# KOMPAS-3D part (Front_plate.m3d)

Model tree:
1. X Axis
2. Y Axis
3. Z Axis
4. Origin
     Wall Thickness 1 = 1; Wall Thickness 2 = 1; Distance 1 = 10; Distance 2 = 10

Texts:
  Steel DIN 17102
  Three Point Plane
  Plane at Angle
  Line and Point Plane
  Axis through Two Vertices
  Axis of Feature
  Axis of Conical Surface
  Axis through Edge
  Trim by Surface
  Trim by Sketch
  Feature with No History
  Intersection Axis of Two Planes
  Two Line Plane
  Line and Face Plane
  Bend by line
  Hole in sheet body
  Cut in sheet body
  Point in CM
  Linear Dimension from Line to Point
  Surface Finish Symbol
  Geometric Tolerance Symbol
  Leader #1
  Leader #2
  Leader #3
  Shape Deviations and Datum
  Node point number
  Mark of coordination axis
  Node point designation
  Mark/Reference designation with leader
  Mark/reference designation on line
  Mark/Reference designation without leader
